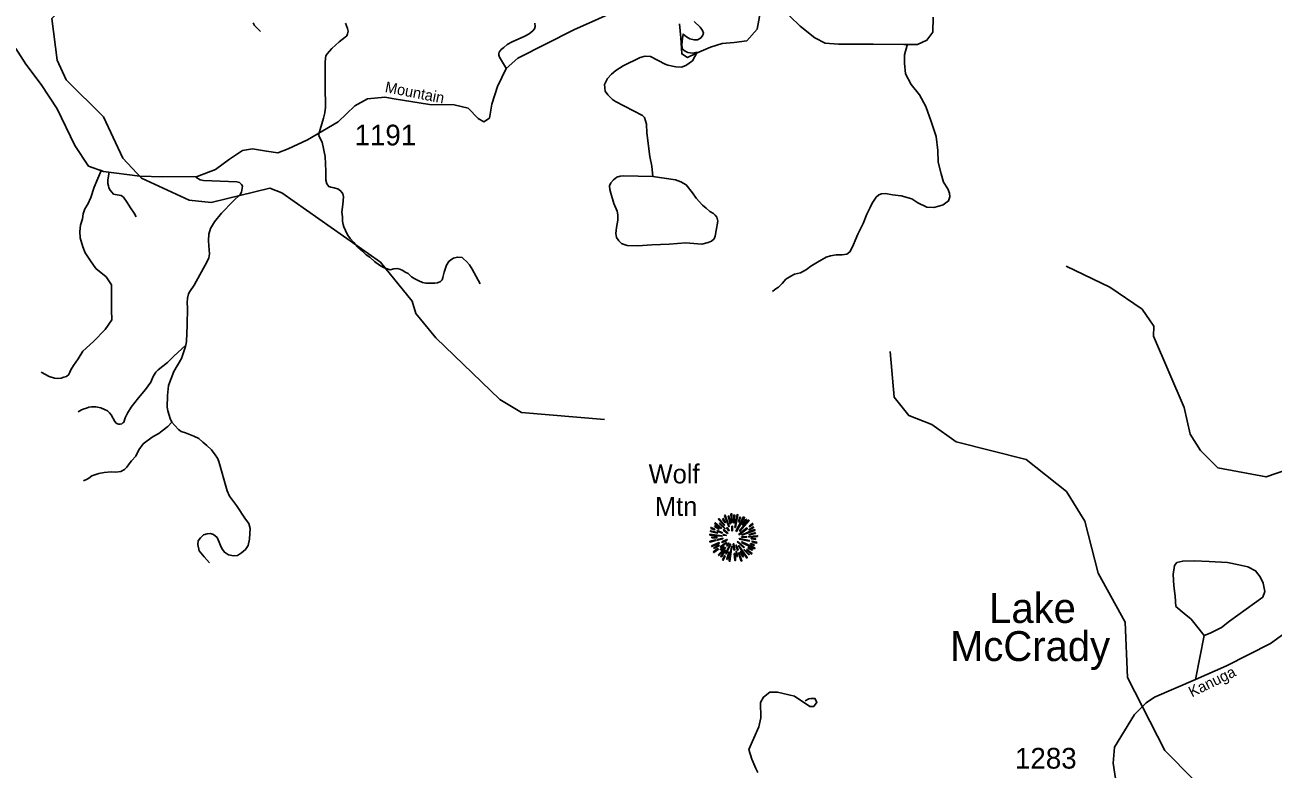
# Model space of a CAD drawing. Extents: x 884530 to 1028605, y 526725 to 653634.
# Drawn here: x 944614 to 952140, y 571686 to 576177 of the extents above; entities that cross this region are included whole.
import ezdxf

# ---------------------------------------------------------------- set-up
doc = ezdxf.new("R2010")
doc.units = 0
for name, color, linetype in [('Exist Geographical Mountain Summit CELL', 7, 'Continuous'), ('Exist Geographical Mountain Summit Label', 7, 'Continuous'), ('Exist Hydrographic Creek Single Shore', 7, 'Continuous'), ('Exist Hydrographic Lake Shore Label', 7, 'Continuous'), ('Exist Road Non-System Type 51', 7, 'Continuous'), ('Exist Road Secondary Type 51 Attributed', 7, 'Continuous'), ('Exist Road Secondary Type 51 Label', 7, 'Continuous'), ('Exist Road Secondary Type 51 Number Label', 7, 'Continuous')]:
    doc.layers.add(name, color=color, linetype=linetype)

msp = doc.modelspace()

# ---------------------------------------------------------------- linework, layer by layer
at = {"layer": 'Exist Geographical Mountain Summit CELL'}
for points in [[(948831.9, 573216.8), (948858.1, 573149.9), (948861, 573150.9), (948837, 573219.3)], [(948865.7, 573164.8), (948868.2, 573165.5), (948859.2, 573213.5), (948854.8, 573212.4)], [(948870.4, 573226.2), (948874.5, 573174.2), (948877.7, 573174.6), (948876.3, 573227.3)], [(948886.5, 573172.1), (948890.4, 573172.1), (948894, 573219.3), (948888.6, 573219.3)], [(948898.4, 573143.7), (948913.3, 573220.7), (948907.8, 573222.5), (948895.2, 573144.4)], [(948750.2, 573139), (948772.6, 573130.3), (948773.8, 573133.2), (948751.6, 573144.1)], [(948772, 573149.9), (948797.8, 573133.5), (948800, 573136.1), (948774.8, 573153.9)], [(948773, 573168.8), (948812.7, 573138.2), (948814.9, 573140.4), (948776.7, 573173.2)], [(948793.4, 573193.5), (948829.4, 573156.1), (948832.7, 573158.6), (948797.4, 573198.2)], [(948801.4, 573165.8), (948834.1, 573136.8), (948836.3, 573139), (948804.3, 573171)], [(948821, 573195), (948836.6, 573173.2), (948838.4, 573174.6), (948825, 573199)], [(948844.7, 573140.4), (948858.5, 573124), (948860.6, 573126.2), (948847.9, 573143.4)], [(948875.9, 573152.8), (948877.3, 573123.7), (948879.9, 573124), (948879.9, 573153.1)], [(948901.7, 573121.9), (948904.6, 573120.1), (948953.3, 573204.7), (948947.8, 573208.4)], [(948916.2, 573178.9), (948919.5, 573177.8), (948929, 573204.7), (948924.2, 573206.5)], [(948919.5, 573103.4), (948921.3, 573100.8), (948970, 573136.8), (948966.8, 573141.2)], [(948922.7, 573123.3), (948925, 573121.2), (948980.5, 573185.5), (948976.5, 573190.2)], [(948960.2, 573195), (948939.1, 573161.5), (948942.1, 573160.4), (948964.5, 573191.7)], [(948980.5, 573128.5), (949008.1, 573143.4), (949005.2, 573148.4), (948979.1, 573131)], [(948980.5, 573151.3), (948982.4, 573148.8), (949005.2, 573165.1), (949001.6, 573168.8)], [(948743.2, 573060.9), (948744.6, 573055.7), (948780.7, 573066.3), (948778.5, 573069.6)], [(948744.6, 573098.6), (948816.7, 573091.7), (948817, 573094.6), (948744.6, 573103.7)], [(948747.3, 573119.7), (948788.7, 573110.2), (948789.8, 573113.5), (948748.4, 573124.4)], [(948756.7, 573081.2), (948786.5, 573082.7), (948786.5, 573086.3), (948755.6, 573086.3)], [(948788.7, 573121.9), (948819.2, 573109.9), (948820.3, 573112), (948790.9, 573125.9)], [(948789.1, 573072.2), (948790.1, 573067.4), (948823.2, 573075.8), (948822.5, 573079.4)], [(948816.7, 573057.9), (948818.9, 573053.2), (948847.6, 573068.4), (948846.5, 573071.8)], [(948825, 573127.3), (948850.1, 573108.4), (948852.2, 573111.3), (948827.6, 573130.6)], [(948825.3, 573097.6), (948842.4, 573095.3), (948842.8, 573097.6), (948826.1, 573101.9)], [(948920.9, 573074), (948981.7, 573062), (948982.7, 573066.3), (948922, 573077.6)], [(948935.5, 573087.8), (948935.5, 573084.9), (948965.6, 573084.9), (948966.4, 573089.9)], [(948936.5, 573100.5), (948937.6, 573098.2), (949015.8, 573126.9), (949014, 573131.7)], [(948978.7, 573086.7), (949031.1, 573089.9), (949031.4, 573094.6), (948979.1, 573089.9)], [(948982.4, 573100.5), (949019.1, 573107), (949017.6, 573112.4), (948980.9, 573102.7)], [(948993.6, 573074.7), (949020.1, 573072.4), (949020.1, 573076.8), (948994, 573077.9)], [(948997.7, 573057.5), (949026, 573050.3), (949026.7, 573055.7), (948998.7, 573062)], [(948753, 573033.2), (948755.6, 573028.5), (948801, 573048.5), (948799.6, 573053.2)], [(948764.3, 572996.5), (948767.2, 572992.5), (948795.6, 573013.6), (948793, 573016.9)], [(948770.5, 573017.3), (948799.6, 573034), (948797.4, 573037.6), (948768.3, 573022.3)], [(948795.2, 572976.9), (948798.1, 572974.4), (948838.8, 573022), (948835.9, 573024.1)], [(948810.5, 573008.2), (948829.8, 573026.3), (948826.4, 573028.5), (948806.1, 573011.4)], [(948806.8, 573026.7), (948809.7, 573023), (948844.3, 573051.4), (948842.4, 573053.9)], [(948835.2, 573008.2), (948810.1, 572968.9), (948813.3, 572966.4), (948839.2, 573006)], [(948838.4, 572986.7), (948842.8, 572984.9), (948869.4, 573043.4), (948866.8, 573044.2)], [(948845.4, 573036.1), (948848.6, 573033.2), (948858.8, 573049.6), (948856.9, 573051)], [(948850.1, 572951.5), (948862.1, 572994.3), (948858.5, 572994.7), (948845.7, 572952.5)], [(948859.9, 572941.3), (948864.6, 572940.2), (948877.3, 573029.5), (948874.1, 573030.3)], [(948885.3, 573045.2), (948889.3, 573008.2), (948893.7, 573008.5), (948888.6, 573046)], [(948891.5, 572986.7), (948895.2, 572944.2), (948899.2, 572945.2), (948895.8, 572986.7)], [(948901.4, 573036.5), (948910.1, 573006.7), (948914.1, 573008.5), (948903.5, 573037.6)], [(948911.1, 572970), (948905.7, 572999.8), (948902.4, 572999.8), (948906.8, 572968.9)], [(948909.7, 573056.9), (948948.2, 573021.6), (948950.7, 573025.9), (948911.5, 573059.1)], [(948915.9, 573034.3), (948966.4, 572959.5), (948970, 572962.3), (948918.4, 573035.4)], [(948915.9, 572991.5), (948933.3, 572941.6), (948937.6, 572943.4), (948918.8, 572992.2)], [(948926.4, 572997.2), (948942.4, 572967.8), (948946.4, 572970), (948930.1, 572998.7)], [(948934.7, 573054.3), (949012.9, 573016.1), (949014.7, 573021.6), (948936.2, 573057.2)], [(948948.2, 573008.5), (948978.3, 572979.4), (948981.7, 572982), (948950.4, 573011)], [(948964.9, 573009.2), (948995.4, 572983.4), (948998.7, 572987.1), (948966.8, 573011.8)], [(948974, 573020.2), (948999.1, 573007.1), (949001.6, 573010.7), (948976.2, 573024.1)], [(948988.2, 573044.2), (949009.3, 573036.1), (949011.1, 573040.5), (948989.6, 573047.4)], [(948820.3, 572949.6), (948825, 572946.8), (948835.9, 572971.4), (948832.7, 572973.6)]]:
    msp.add_lwpolyline(points, close=True, dxfattribs=at)
at = {"layer": 'Exist Hydrographic Creek Single Shore'}
for points in [[(948107.8, 573795.1), (947609, 573837.9), (947478.5, 573916), (947091.6, 574288.1), (946971.6, 574434.9), (946949.4, 574510.8), (946757.7, 574744.4), (946163.9, 575163.3), (946089.8, 575191), (945736.5, 575106.2), (945603.7, 575118.8), (945316.6, 575252.5), (945204.2, 575372.9), (945087.9, 575621.3), (944862.6, 575845.7), (944808.3, 575965), (944775.6, 576215.1), (944793, 576231.1)], [(955625.8, 572471.2), (954889.6, 572847), (954533, 573003.3), (953703.8, 573242.3), (953486.6, 573346.3), (953274.1, 573511.6), (953014.5, 573587.2), (952609.8, 573533.9), (952483.1, 573487.2), (952233.3, 573495.5), (952098.2, 573449), (951808.3, 573504.1), (951703.5, 573607.9), (951640.6, 573707.6), (951604.6, 573869.1), (951419.8, 574299.5), (951422.1, 574358.5), (951350.5, 574461.7), (951155.3, 574593.6), (950892.7, 574720.2)], [(952404.2, 571053.8), (952380.8, 571106.8), (952009.5, 571209.4), (951834.5, 571449.2), (951488.4, 571797.5), (951262.5, 572238.5), (951249.5, 572573.5), (951085, 572868.9), (951004.4, 573182.2), (950894.2, 573361.7), (950650.9, 573553.6), (950229.5, 573660.5), (950083.1, 573765.2), (949943.4, 573820.5), (949855.5, 573930.6), (949832.1, 574206.7)]]:
    msp.add_lwpolyline(points, dxfattribs=at)
at = {"layer": 'Exist Road Non-System Type 51'}
for points in [[(945990.8, 576189.2), (945997.6, 576173.1), (946035.2, 576136.3)], [(946383.1, 575511.6), (946413.6, 575614.4), (946421.7, 575646.7), (946427.2, 575679.7), (946426.5, 575713.5), (946425, 575775.7), (946424.1, 575863.9), (946424.1, 575925.3), (946424.1, 575950.5), (946425.7, 575976.7), (946428.8, 575990.5), (946437.2, 576002.7), (946465.2, 576034.7), (946509.2, 576075.6), (946543.9, 576103.3), (946554.6, 576111.7), (946559.9, 576123.9), (946562.2, 576139.3), (946559.9, 576155.4), (946546.9, 576186.5)], [(947689.1, 576186.7), (947689.8, 576168.1), (947686.3, 576153.1), (947677, 576141.8), (947655, 576123.9), (947628.1, 576107.9), (947551.5, 576073.9), (947521.5, 576057.6), (947500.7, 576041.2), (947486.5, 576027.6), (947473.7, 576012), (947471.7, 576003.4), (947471.7, 575993.4), (947475.1, 575981.9), (947518.2, 575912.5)], [(948583, 576121.2), (948603.8, 576104.8), (948623.7, 576091.9), (948648.8, 576085.8), (948668.6, 576087.5), (948688.5, 576097), (948700.6, 576110.9), (948704.9, 576126.4), (948698.9, 576143.7), (948686, 576162.7), (948648.8, 576198.2)], [(948667.7, 576012.3), (948639.4, 576007.3), (948611.5, 576009.8), (948594.3, 576017.5), (948579.7, 576031.3), (948574.9, 576053.1), (948577, 576081.5), (948583, 576121.5), (948583, 576122.1)], [(948667.7, 576012.3), (948640.1, 575960.1), (948600, 575932.6), (948573.2, 575922.5), (948539.3, 575924.5), (948491.5, 575933.4), (948474.6, 575939.4), (948386.3, 575986.2), (948354.7, 575988.4), (948323.2, 575979.2), (948220.8, 575929.6), (948177, 575901.5), (948150.8, 575879.9), (948126.1, 575853.6), (948108.9, 575818.2), (948112.6, 575777.9), (948128.8, 575754), (948156, 575727.5), (948175.8, 575714.4), (948338.8, 575631), (948350.6, 575617.9), (948361.7, 575577.3), (948363.3, 575525.3), (948382.5, 575382.2), (948393.8, 575324.3), (948400.6, 575261.2), (948222.5, 575265.9), (948202.5, 575264.9), (948182.7, 575257.6), (948162, 575241.6), (948146.8, 575224.1), (948138.9, 575206.1), (948140.2, 575183.1), (948146, 575161.5), (948165.5, 575098.7), (948185.4, 575053.8), (948189.7, 575031.2), (948188.9, 574997.6), (948181.1, 574953.4), (948177.6, 574918), (948181.1, 574894.7), (948195, 574873.1), (948210.5, 574857.5), (948226.8, 574851.7), (948245.1, 574846.2), (948309.8, 574842.8), (948393.5, 574850.4), (948499.5, 574853.6), (948599, 574862.2), (948695.6, 574854.4), (948734.3, 574864.5), (948753.2, 574872.4), (948771, 574886.1), (948775.6, 574902.4), (948781.4, 574937.1), (948791.4, 574992.4), (948787.1, 575015.7), (948776.7, 575028.7), (948765.4, 575038.2), (948743.8, 575051.1), (948721.5, 575071.1), (948699.7, 575089.3), (948661, 575132.2), (948638.6, 575164), (948601.2, 575211.1), (948569.3, 575230.9), (948536.4, 575241.3), (948400.6, 575261.2)], [(949933.2, 576055.3), (949917.3, 575995.8), (949917.3, 575945.6), (949924, 575881.9), (949957.5, 575818.2), (950009.1, 575754.9), (950045.5, 575685.3), (950078.2, 575593.6), (950108.3, 575503.1), (950118.4, 575419.4), (950121.7, 575348.9), (950139.9, 575277.6), (950153.2, 575227.8), (950179.6, 575188.2), (950189.7, 575162.2), (950190.6, 575138.4), (950183.3, 575114.5), (950151.6, 575090.4), (950124.8, 575083.1), (950093.8, 575074.8), (950052.2, 575076.1), (949998.3, 575103.8), (949962.2, 575127.3), (949898, 575144.5), (949846.1, 575150.9), (949803.2, 575159.2), (949780.1, 575157.9), (949763.1, 575152.2), (949746.6, 575137.7), (949723, 575100.8), (949710.5, 575074.8), (949689.7, 575034.6), (949669.3, 574979), (949653.7, 574950.9), (949636.6, 574914.4), (949620.5, 574876.4), (949610.7, 574852.5), (949600.4, 574829.6), (949588.4, 574807.1), (949570.8, 574793.9), (949541.9, 574788.6), (949505.7, 574789.7), (949472.4, 574784.2), (949444.5, 574775.1), (949392.3, 574745.5), (949352.1, 574720.5), (949327, 574701.3), (949291.3, 574680.5), (949255.3, 574672.1), (949231.7, 574661.1), (949202.7, 574643.1), (949180.6, 574616.7), (949158.4, 574594.6), (949135.7, 574580.4), (949121.1, 574568.3)], [(946383.1, 575511.6), (946406.7, 575469.9), (946423.3, 575383.3), (946426.6, 575338.9), (946429, 575295.2), (946427.8, 575267.1), (946429, 575239.9), (946434.1, 575218.1), (946445.7, 575202.4), (946459.1, 575197.2), (946478, 575194.1), (946504, 575184.7), (946521.6, 575171.1), (946530.1, 575156.6), (946535.3, 575138.8), (946531.1, 575094), (946524.8, 575047.1), (946528.1, 575018.6), (946528.1, 574993.2), (946532.1, 574972), (946537.5, 574958.3), (946547.1, 574936.1), (946559.8, 574910.7), (946575.6, 574888.6), (946594.6, 574866.4), (946620, 574837.8), (946648.6, 574812.5), (946670.7, 574790.3), (946693, 574774.4), (946721.5, 574749), (946752, 574727.1), (946776, 574713.5), (946798, 574704.1), (946816.6, 574698.2), (946838.9, 574704.6), (946857.8, 574707.8), (946875.2, 574703.1), (946891.8, 574694.8), (946907.5, 574685.4), (946924.5, 574676), (946945, 574657.2), (946965.8, 574644.7), (946988.8, 574632.2), (947010.6, 574622.8), (947030.5, 574618.6), (947051.3, 574618.6), (947072.1, 574617.6), (947085.6, 574617.6), (947101.3, 574619.7), (947119.1, 574629), (947130.5, 574639.5), (947133.7, 574653.2), (947141.4, 574685.7), (947155.5, 574727.7), (947169.4, 574749.7), (947181.4, 574759.7), (947197.4, 574769.7), (947221.4, 574775.7), (947249.5, 574773.7), (947259.4, 574765.7), (947277.5, 574749.7), (947295.4, 574729.7), (947311.4, 574703.7), (947359.4, 574613.7)], [(945076.3, 575302.8), (945031.3, 575197.4), (945010.9, 575136.2), (944993.1, 575095.4), (944975.1, 575067.4), (944965, 575036.7), (944959.9, 575006.2), (944949.7, 574967.9), (944944.6, 574929.7), (944947.2, 574891.4), (944962.4, 574837.8), (944977.7, 574802.1), (945008.4, 574753.7), (945041.5, 574707.7), (945102.8, 574656.8), (945135.9, 574608.3), (945135.9, 574544.6), (945135.9, 574455.3), (945138.5, 574396.6), (945097.7, 574337.9), (945026.2, 574266.5), (944962.4, 574207.9), (944934.3, 574161.9), (944906.3, 574121.1), (944891.3, 574094.7), (944878.4, 574067.5), (944865.3, 574056.2), (944848.9, 574051), (944831.7, 574045), (944810.9, 574043.3), (944791.5, 574044.6), (944760.8, 574055.4), (944711.5, 574081.3)], [(945122.6, 575288.9), (945113.7, 575241.6), (945114.5, 575220.3), (945117.5, 575205.7), (945120.3, 575194.5), (945127.9, 575179.9), (945137.5, 575166.6), (945147.6, 575156.2), (945158.4, 575152.8), (945169.8, 575151.4), (945193.1, 575148.4), (945207.7, 575136.8), (945230, 575105.8), (945250.3, 575072.9), (945271.6, 575039.9), (945285.3, 575019.5)], [(945643.9, 575259), (945671.1, 575242.5), (945690.5, 575238.6), (945892.1, 575229.7), (945907.4, 575225.1), (945920.6, 575214.3), (945925.2, 575202.8), (945924.2, 575191.5), (945919.7, 575166.6), (945912.5, 575153.9), (945869.9, 575113.6), (945799, 575041.8), (945757.4, 574988.5), (945733.2, 574947.7), (945723.5, 574914.8), (945720.6, 574876.1), (945722.5, 574843.1), (945727.3, 574795.5), (945722.5, 574770.4), (945713.6, 574748.3), (945633.3, 574606.5), (945608.3, 574568.2), (945600, 574554.3), (945594.1, 574528.2), (945592.5, 574498.9), (945594.9, 574468.8), (945592.5, 574365.2), (945589, 574266.1), (945584.4, 574245.1)], [(945584.4, 574245.1), (945512.5, 574177.5), (945474.3, 574138.8), (945417.4, 574095.4), (945403.3, 574081.2), (945389.1, 574059.5), (945380.2, 574041.5), (945373.8, 574021), (945340.4, 573977.3), (945298.1, 573927.2), (945255.3, 573870.4), (945233, 573834.1), (945218.5, 573806.7), (945209.2, 573779.3), (945204.1, 573774.7), (945197.9, 573770.6), (945186.5, 573767.6), (945179.9, 573767.3), (945172.2, 573769.4), (945163.9, 573774.3), (945156.8, 573783), (945133.8, 573823.2), (945123.2, 573835.6), (945110.7, 573847.7), (945094.3, 573857.1), (945072.2, 573865.6), (945041.4, 573872), (945029.8, 573873.1), (945014.4, 573872), (944999.3, 573869.6), (944984.9, 573864.9), (944970, 573860.2), (944953.9, 573853.1), (944934.9, 573841.2)], [(945584.4, 574245.1), (945582.4, 574236.4), (945558.4, 574163.9), (945511.7, 574084.6), (945480.2, 574001.1), (945473.4, 573941.2), (945472.1, 573871.2), (945475, 573848.6), (945489.4, 573802.1), (945498.9, 573779.6)], [(945498.9, 573779.6), (945475.2, 573753.1), (945440.3, 573727.7), (945420.3, 573710.5), (945386.4, 573692.9), (945351.5, 573667.5), (945326.1, 573648.4), (945300.8, 573613.6), (945281.8, 573575.5), (945256.5, 573547.1), (945241.4, 573527.5), (945227.5, 573509.1), (945214.7, 573493.8), (945192.5, 573482.1), (945162, 573478.2), (945133, 573480.1), (945092.5, 573476.5), (945059, 573470.1), (945016.8, 573455.6), (944999.3, 573442.5), (944989.1, 573435.2), (944967.4, 573426.5)], [(945498.9, 573779.6), (945517.1, 573759.8), (945539.7, 573736.4), (945556, 573722.6), (945582.7, 573714.7), (945633, 573695.8), (945662.3, 573680.3), (945687.4, 573659.5), (945711.6, 573638.7), (945738.3, 573612.8), (945760, 573582.5), (945774.5, 573562), (945782.5, 573542.8), (945833, 573365.7), (945848.1, 573332.6), (945889.7, 573276.7), (945943.8, 573195.1), (945963.3, 573168.7), (945971, 573138.3), (945970.3, 573107.2), (945967.1, 573073), (945960.1, 573034.9), (945943, 573010.8), (945920.4, 572990.6), (945896.3, 572975.8), (945872.2, 572972.7), (945841.9, 572978.9), (945816.3, 572995.2), (945801.5, 573017.1), (945793.7, 573034.9), (945785.9, 573055.9), (945772.7, 573084.7), (945751, 573101.8), (945733, 573107.2), (945712.1, 573105.6), (945691.1, 573099.4), (945672.4, 573081.5), (945659.2, 573062.9), (945656, 573041.1), (945664.6, 573003), (945694.2, 572967.2), (945727.6, 572929.9)], [(951673.2, 572226.6), (951724.3, 572491.4), (951760.4, 572505.6), (951828.6, 572541.6), (951877.9, 572579.5), (952078, 572724.6), (952090.3, 572758.8), (952079.9, 572809), (952062.9, 572847), (952034.7, 572883.5), (951988.4, 572906.6), (951934.6, 572918.2), (951865.2, 572933.6), (951754.7, 572939.9), (951664.7, 572942.7), (951595.7, 572941.3), (951560.9, 572933.6), (951545.5, 572914.3), (951537.8, 572860.4), (951541.7, 572791.1), (951549.4, 572729.4), (951553.2, 572667.8), (951603.9, 572624.3), (951645.7, 572590.8), (951677.9, 572551.1), (951724.3, 572491.4)], [(949033.1, 571665.6), (949021.2, 571689.3), (948997.5, 571745.5), (948979.9, 571804.1), (949038.5, 571940.8), (949052.1, 571995.3), (949049.3, 572087.9), (949068.4, 572120.6), (949106, 572150.2), (949152.5, 572150.2), (949253.7, 572126), (949346.1, 572063.4), (949370.7, 572063.4), (949389.8, 572090.6), (949377.2, 572113.2), (949354.3, 572112.4), (949340.7, 572109.7), (949319, 572098.7)]]:
    msp.add_lwpolyline(points, dxfattribs=at)
at = {"layer": 'Exist Road Secondary Type 51 Attributed'}
for points in [[(948221.4, 576278.9), (947924.7, 576147), (947585.5, 575976.1), (947514.9, 575914.6), (947462.5, 575805.2), (947428.4, 575699.1), (947414.8, 575614.8), (947380.6, 575592), (947346.5, 575612.5), (947287.3, 575674), (947203, 575694.5), (947052.8, 575696.8), (946841, 575731), (946784.8, 575740.1), (946680.1, 575731), (946602.6, 575687.7), (946502.5, 575592), (946318, 575482.7), (946200.9, 575428.1), (946139.4, 575405.4), (946071.1, 575414.5), (945986.9, 575428.1), (945925.4, 575419), (945848, 575366.6), (945763.7, 575305.1), (945652.2, 575261.8), (945445, 575259.5), (945306.1, 575264.1), (945087.5, 575291.4), (944998, 575324.5), (944914.5, 575448.6), (944808.8, 575669.4), (944710.9, 575817.5), (944619.8, 575940.6), (944558.3, 576034)], [(949050.1, 576260.7), (949029.6, 576151.3), (948967.7, 576081.5), (948890.7, 576071.6), (948817.9, 576064.7), (948747.3, 576042), (948663.1, 576005.5), (948608.4, 575980.4), (948574.1, 576002.1), (948569.2, 576097.9), (948560.6, 576183.2)], [(950091.5, 576224), (950089.2, 576132.9), (950052.8, 576085), (949995.8, 576057.7), (949913.9, 576057.7), (949729, 576061.1), (949607.9, 576060.2), (949519.1, 576060.2), (949439.5, 576067), (949378, 576098.9), (949289.2, 576169.6), (949164, 576290.3)], [(951195.5, 571589.8), (951175.6, 571722.6), (951183.5, 571818.3), (951304.7, 572015.6), (951374.2, 572085.1), (951425.4, 572120.9), (951673.2, 572226.6), (951860.6, 572309.8), (952124.9, 572443.2), (952322.2, 572587.2)]]:
    msp.add_lwpolyline(points, dxfattribs=at)

# ---------------------------------------------------------------- texts
at = {"layer": 'Exist Geographical Mountain Summit Label'}
for s, p in [('Wolf', (948374.7, 573410.3)), ('Mtn', (948412.8, 573214.2))]:
    msp.add_text(s, height=114.83, dxfattribs=at).set_placement(p)
at = {"layer": 'Exist Hydrographic Lake Shore Label'}
for s, p in [('Lake', (950428.3, 572568)), ('Lake', (950428.3, 572568)), ('McCrady', (950192.3, 572338.3)), ('McCrady', (950192.3, 572338.3))]:
    msp.add_text(s, height=180.45, dxfattribs=at).set_placement(p)
at = {"layer": 'Exist Road Secondary Type 51 Label'}
for s, rotation, p in [('Mountain', 348.93249, (946781.3, 575771.9)), ('Kanuga', 26.04824, (951650.9, 572118))]:
    msp.add_text(s, height=65.62, rotation=rotation, dxfattribs=at).set_placement(p)
at = {"layer": 'Exist Road Secondary Type 51 Number Label'}
for s, p in [('1191', (946601.4, 575449.7)), ('1283', (950584.1, 571689.2))]:
    msp.add_text(s, height=125, dxfattribs=at).set_placement(p)

doc.saveas('drawing.dxf')
